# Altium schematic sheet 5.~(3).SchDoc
size 420 x 297 mm
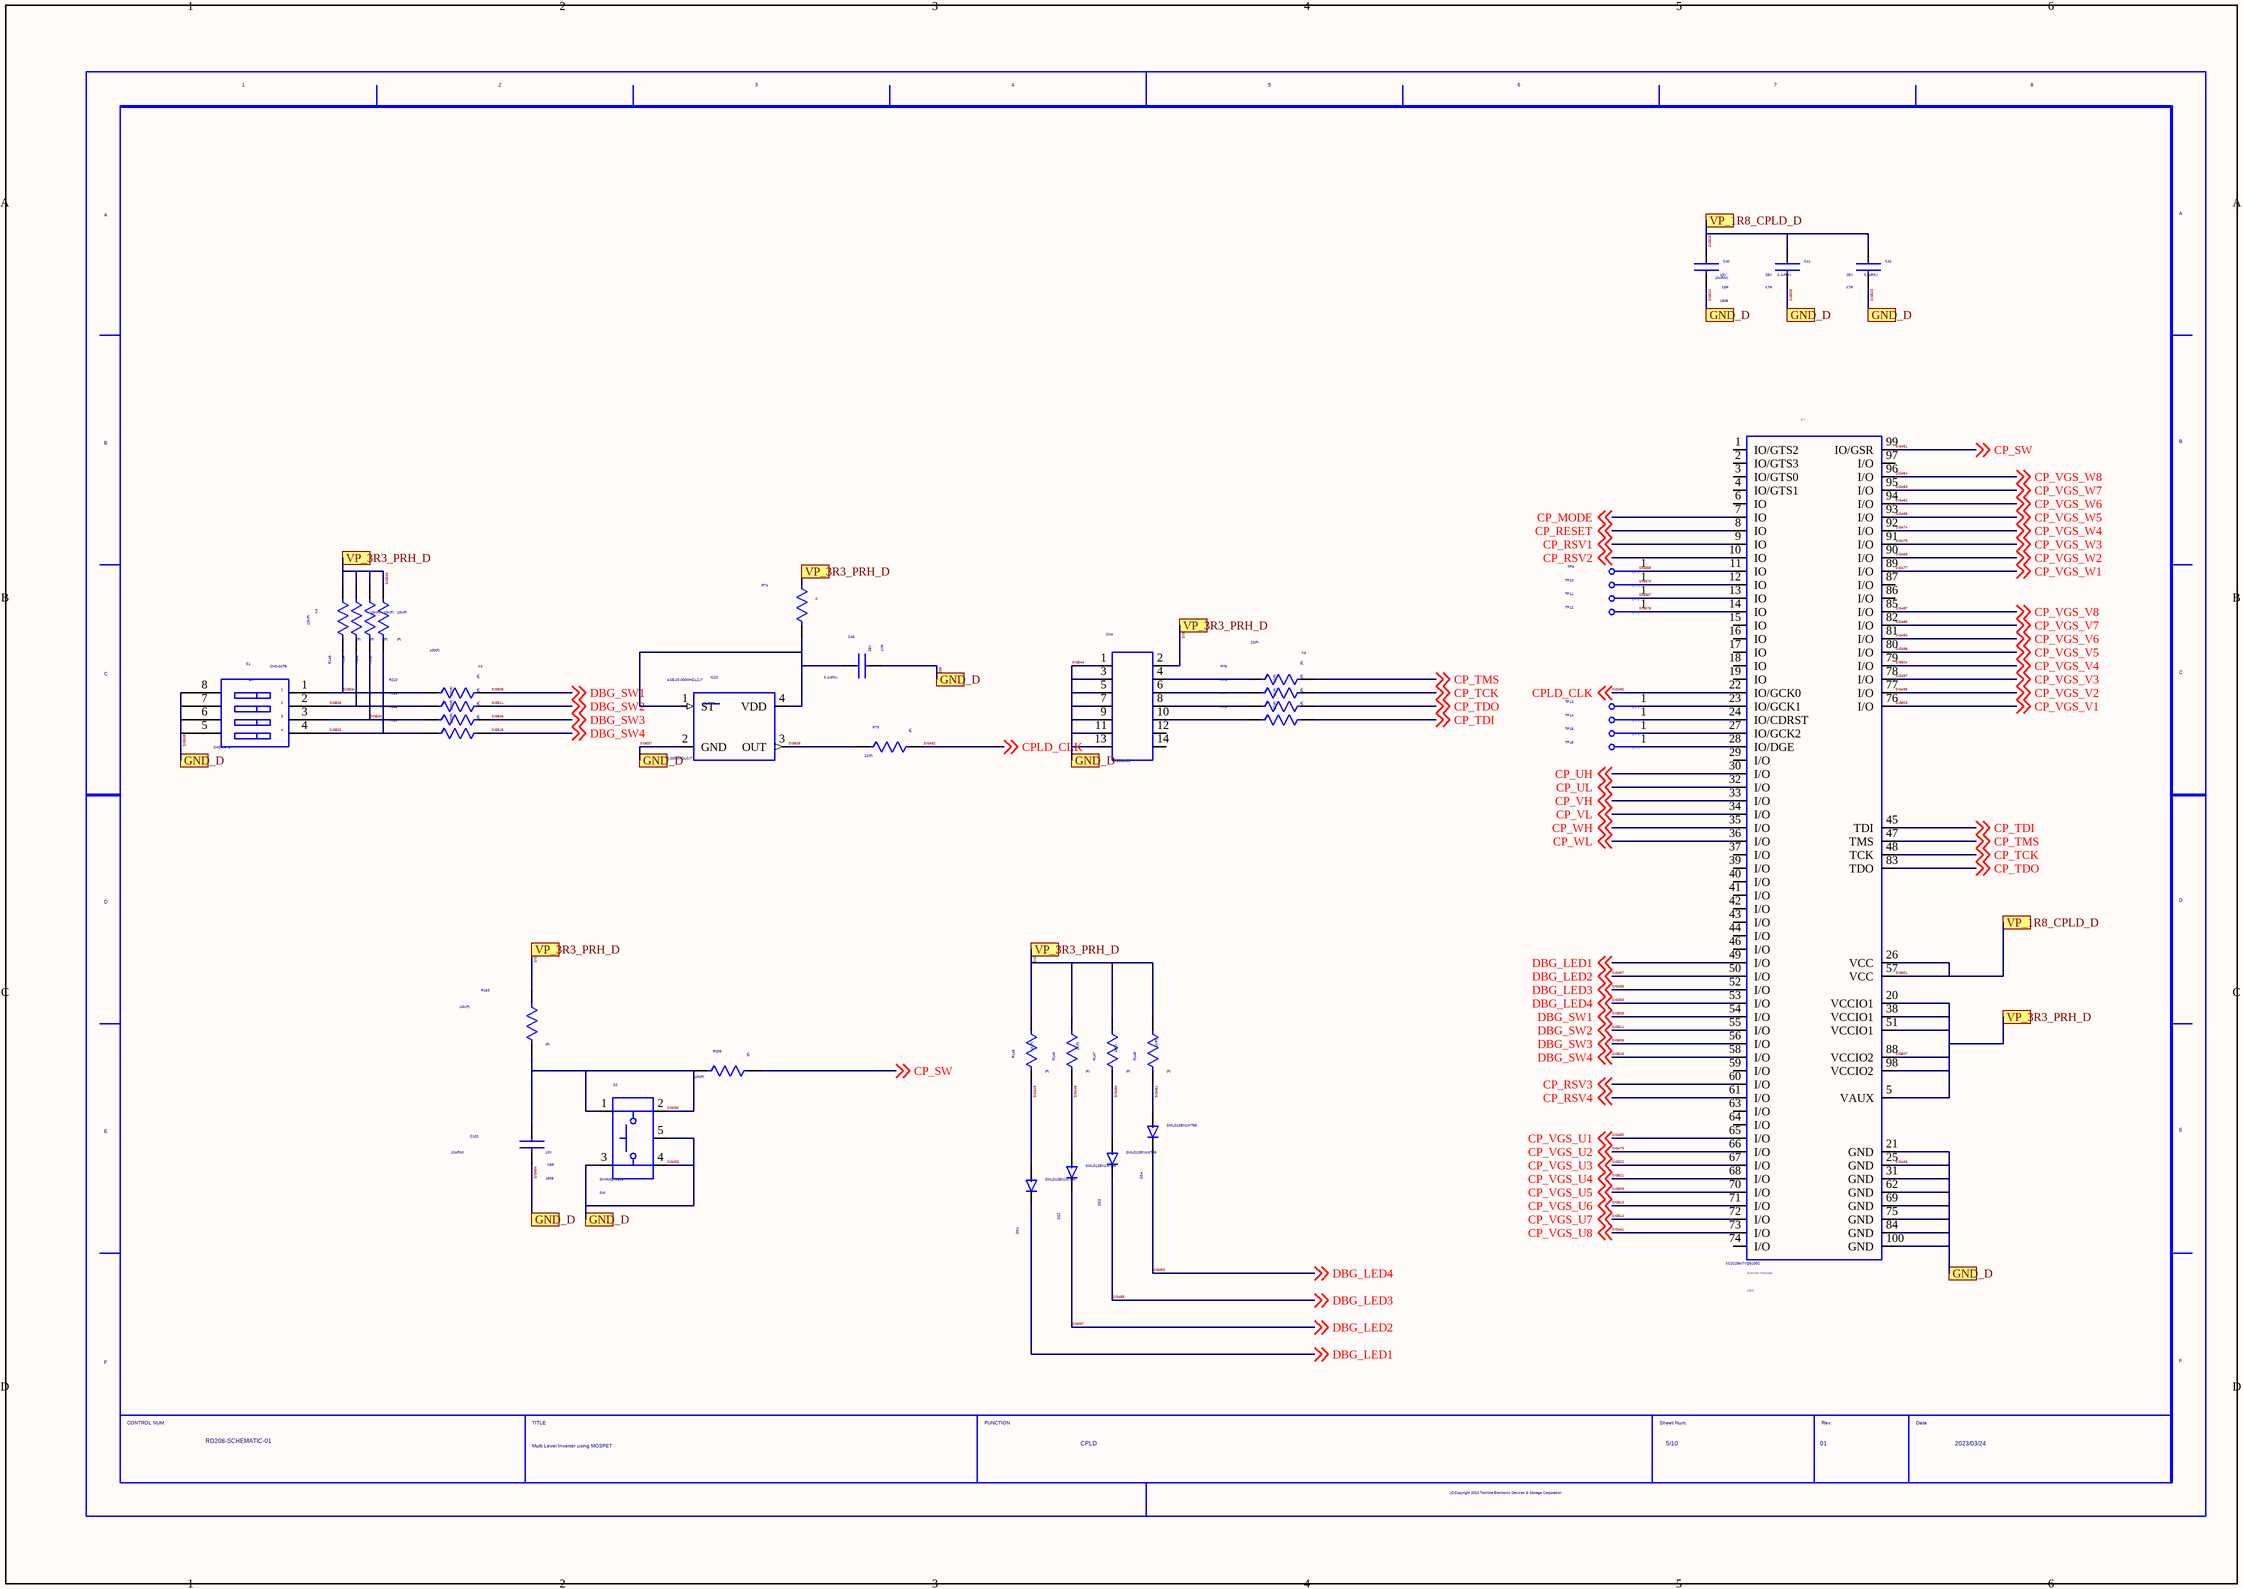
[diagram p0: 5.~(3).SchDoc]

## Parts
C40  VAL2: 10V  SIZECODESMD: 1608  VALUE4: X5R  VAL1: 10uF(M)  (hidden comment: GRM188R61A106ME69D)
C41  VAL2: 25V  VALUE4: X7R  VAL1: 0.1uF(K)  (hidden comment: GRM155R71E104KE14D)
C42  VAL2: 25V  VALUE4: X7R  VAL1: 0.1uF(K)  (hidden comment: GRM155R71E104KE14D)
C46  VAL2: 25V  VALUE4: X7R  VAL1: 0.1uF(K)  (hidden comment: GRM155R71E104KE14D)
C102  VAL2: 10V  SIZECODESMD: 1608  VALUE4: X5R  VAL1: 10uF(M)  (hidden comment: GRM188R61A106ME69D)
CN4  VAL1: 878311420  (hidden comment: 0878311420)
DS1  SMLD12EN1WT86
DS2  SMLD12EN1WT86
DS3  SMLD12EN1WT86
DS4  SMLD12EN1WT86
IC7  VAL2: CPLD  VAL1: XC2C256-7VQG100C  (hidden comment: XC2C256_7VQG100C)
IC22  VAL1: ASE-20.000MHZ-LC-T  (hidden comment: ASE_20_000MHZ_LC_T)
R74  VAL1: 0  (hidden comment: ERJ2GE0R00X)
R75  VALUE4: (F)  VAL1: 22(F)  (hidden comment: ERJ2RKF22R0X)
R76  VALUE4: (F)  VAL1: 22(F)  (hidden comment: ERJ2RKF22R0X)
R77  VALUE4: (F)  VAL1: 22(F)  (hidden comment: ERJ2RKF22R0X)
R78  VALUE4: (F)  VAL1: 22(F)  (hidden comment: ERJ2RKF22R0X)
R79  VALUE4: (F)  VAL1: 22(F)  (hidden comment: ERJ2RKF22R0X)
R145  VALUE4: (F)  VAL1: 1k(F)  (hidden comment: ERJ2RKF1001X)
R146  VALUE4: (F)  VAL1: 1k(F)  (hidden comment: ERJ2RKF1001X)
R147  VALUE4: (F)  VAL1: 1k(F)  (hidden comment: ERJ2RKF1001X)
R148  VALUE4: (F)  VAL1: 1k(F)  (hidden comment: ERJ2RKF1001X)
R149  VALUE4: (F)  VAL1: 10k(F)  (hidden comment: ERJ2RKF1002X)
R150  VALUE4: (F)  VAL1: 10k(F)  (hidden comment: ERJ2RKF1002X)
R151  VALUE4: (F)  VAL1: 10k(F)  (hidden comment: ERJ2RKF1002X)
R152  VALUE4: (F)  VAL1: 10k(F)  (hidden comment: ERJ2RKF1002X)
R153  VALUE4: (F)  VAL1: 10k(F)  (hidden comment: ERJ2RKF1002X)
R209  VALUE4: (F)  VAL1: 100(F)  (hidden comment: ERJ2RKF1000X)
R210  VALUE4: (F)  VAL1: 100(F)  (hidden comment: ERJ2RKF1000X)
R211  VALUE4: (F)  VAL1: 100(F)  (hidden comment: ERJ2RKF1000X)
R212  VALUE4: (F)  VAL1: 100(F)  (hidden comment: ERJ2RKF1000X)
R213  VALUE4: (F)  VAL1: 100(F)  (hidden comment: ERJ2RKF1000X)
S1  SCH_NAME: CHS-04TB  (hidden comment: CHS_04TB)
S2  VAL2: SW  (hidden comment: SKHMQKE010)
TP9  TP  (value not drawn)
TP10  TP  (value not drawn)
TP11  TP  (value not drawn)
TP12  TP  (value not drawn)
TP13  TP  (value not drawn)
TP14  TP  (value not drawn)
TP15  TP  (value not drawn)
TP16  TP  (value not drawn)
U?  DATE: 2023/03/24  REVISION: 01  SHEETNUMBER: 5/10  FUNCTION: CPLD  TITLE: Multi Level Inverter using MOSFET  DRAWINGNUMBER: RD208-SCHEMATIC-01  (hidden comment: WAKU_DEF100)

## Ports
GND_D, VP_1R8_CPLD_D, VP_3R3_PRH_D

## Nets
CP_MODE: IC7.7(IO) ; off-sheet CP_MODE
CP_RESET: IC7.8(IO) ; off-sheet CP_RESET
CP_RSV1: IC7.9(IO) ; off-sheet CP_RSV1
CP_RSV2: IC7.10(IO) ; off-sheet CP_RSV2
CP_RSV3: IC7.60(I/O) ; off-sheet CP_RSV3
CP_RSV4: IC7.61(I/O) ; off-sheet CP_RSV4
CP_TCK: IC7.48(TCK) R75.2 ; off-sheet CP_TCK
CP_TDI: IC7.45(TDI) R78.2 ; off-sheet CP_TDI
CP_TDO: IC7.83(TDO) R77.2 ; off-sheet CP_TDO
CP_TMS: IC7.47(TMS) R76.2 ; off-sheet CP_TMS
CP_UH: IC7.30(I/O) ; off-sheet CP_UH
CP_UL: IC7.32(I/O) ; off-sheet CP_UL
CP_VH: IC7.33(I/O) ; off-sheet CP_VH
CP_VL: IC7.34(I/O) ; off-sheet CP_VL
CP_WH: IC7.35(I/O) ; off-sheet CP_WH
CP_WL: IC7.36(I/O) ; off-sheet CP_WL
DBG_LED1: DS1.K(C) IC7.49(I/O) ; off-sheet DBG_LED1
SIG448: DS2.A R146.2
SIG449: DS1.A R145.2
SIG450: DS3.A R147.2
SIG451: DS4.A R148.2
SIG453: DS4.K(C) IC7.53(I/O) ; off-sheet DBG_LED4  [also labelled DBG_LED4]
SIG454: C40.2 C41.2 C42.2 C46.2 C102.2 CN4.1 CN4.3 CN4.5 CN4.7 CN4.9 CN4.11 CN4.13 IC7.21(GND) IC7.25(GND) IC7.31(GND) IC7.62(GND) IC7.69(GND) IC7.75(GND) IC7.84(GND) IC7.100(GND) IC22.2(GND) S1.5 S1.6 S1.7 S1.8 S2.3 S2.4 S2.5 ; port GND_D  [also labelled SIG459, SIG466, SIG523, SIG524, SIG525, SIG537, SIG538, SIG539, SIG544]
SIG455: DS3.K(C) IC7.52(I/O) ; off-sheet DBG_LED3  [also labelled DBG_LED3]
SIG456: C102.1 R153.2 R209.1 S2.1 S2.2
SIG457: DS2.K(C) IC7.50(I/O) ; off-sheet DBG_LED2  [also labelled DBG_LED2]
SIG458: CN4.2 IC7.5(VAUX) IC7.20(VCCIO1) IC7.38(VCCIO1) IC7.51(VCCIO1) IC7.88(VCCIO2) IC7.98(VCCIO2) R74.1 R145.1 R146.1 R147.1 R148.1 R149.1 R150.1 R151.1 R152.1 R153.1 ; port VP_3R3_PRH_D  [also labelled SIG460, SIG507, SIG531, SIG549]
SIG461: IC7.99(IO/GSR) R209.2 ; off-sheet CP_SW  [also labelled CP_SW]
SIG462: IC7.94(I/O) ; off-sheet CP_VGS_W6  [also labelled CP_VGS_W6]
SIG463: IC7.95(I/O) ; off-sheet CP_VGS_W7  [also labelled CP_VGS_W7]
SIG464: IC7.96(I/O) ; off-sheet CP_VGS_W8  [also labelled CP_VGS_W8]
SIG465: IC7.93(I/O) ; off-sheet CP_VGS_W5  [also labelled CP_VGS_W5]
SIG467: IC7.13(IO) TP11.1
SIG468: IC7.11(IO) TP9.1
SIG469: IC7.90(I/O) ; off-sheet CP_VGS_W2  [also labelled CP_VGS_W2]
SIG470: IC7.24(IO/CDRST) TP14.1
SIG471: IC7.23(IO/GCK1) TP13.1
SIG472: IC7.28(IO/DGE) TP16.1
SIG473: IC7.12(IO) TP10.1
SIG474: IC7.92(I/O) ; off-sheet CP_VGS_W4  [also labelled CP_VGS_W4]
SIG475: IC7.91(I/O) ; off-sheet CP_VGS_W3  [also labelled CP_VGS_W3]
SIG476: IC7.27(IO/GCK2) TP15.1
SIG477: IC7.89(I/O) ; off-sheet CP_VGS_W1  [also labelled CP_VGS_W1]
SIG478: IC7.14(IO) TP12.1
SIG479: IC7.66(I/O) ; off-sheet CP_VGS_U2  [also labelled CP_VGS_U2]
SIG480: IC7.65(I/O) ; off-sheet CP_VGS_U1  [also labelled CP_VGS_U1]
SIG481: IC7.73(I/O) ; off-sheet CP_VGS_U8  [also labelled CP_VGS_U8]
SIG485: IC7.82(I/O) ; off-sheet CP_VGS_V7  [also labelled CP_VGS_V7]
SIG487: IC7.85(I/O) ; off-sheet CP_VGS_V8  [also labelled CP_VGS_V8]
SIG492: IC7.22(IO/GCK0) R79.2 ; off-sheet CPLD_CLK  [also labelled CPLD_CLK]
SIG493: IC7.81(I/O) ; off-sheet CP_VGS_V6  [also labelled CP_VGS_V6]
SIG495: IC7.77(I/O) ; off-sheet CP_VGS_V2  [also labelled CP_VGS_V2]
SIG497: IC7.78(I/O) ; off-sheet CP_VGS_V3  [also labelled CP_VGS_V3]
SIG498: IC7.80(I/O) ; off-sheet CP_VGS_V5  [also labelled CP_VGS_V5]
SIG501: C40.1 C41.1 C42.1 IC7.26(VCC) IC7.57(VCC) ; port VP_1R8_CPLD_D  [also labelled SIG526]
SIG503: IC7.76(I/O) ; off-sheet CP_VGS_V1  [also labelled CP_VGS_V1]
SIG504: IC7.79(I/O) ; off-sheet CP_VGS_V4  [also labelled CP_VGS_V4]
SIG506: IC7.56(I/O) R212.2 ; off-sheet DBG_SW3  [also labelled DBG_SW3]
SIG508: IC7.54(I/O) R210.2 ; off-sheet DBG_SW1  [also labelled DBG_SW1]
SIG509: IC7.70(I/O) ; off-sheet CP_VGS_U5  [also labelled CP_VGS_U5]
SIG511: IC7.55(I/O) R211.2 ; off-sheet DBG_SW2  [also labelled DBG_SW2]
SIG513: IC7.71(I/O) ; off-sheet CP_VGS_U6  [also labelled CP_VGS_U6]
SIG514: IC7.72(I/O) ; off-sheet CP_VGS_U7  [also labelled CP_VGS_U7]
SIG515: IC7.58(I/O) R213.2 ; off-sheet DBG_SW4  [also labelled DBG_SW4]
SIG521: IC7.68(I/O) ; off-sheet CP_VGS_U4  [also labelled CP_VGS_U4]
SIG522: IC7.67(I/O) ; off-sheet CP_VGS_U3  [also labelled CP_VGS_U3]
SIG530: C46.1 IC22.1(ST) IC22.4(VDD) R74.2
SIG532: R152.2 R213.1 S1.4
SIG533: R151.2 R212.1 S1.3
SIG534: R149.2 R210.1 S1.1
SIG535: IC22.3(OUT) R79.1
SIG536: R150.2 R211.1 S1.2
SIG540: CN4.10 R78.1
SIG541: CN4.6 R75.1
SIG542: CN4.4 R76.1
SIG543: CN4.8 R77.1

Not connected (* = marked no-connect by the designer): CN4 12 14; IC7 1(IO/GTS2) 2(IO/GTS3) 3(IO/GTS0) 4(IO/GTS1) 6(IO) 15(IO) 16(IO) 17(IO) 18(IO) 19(IO) 29(I/O) 37(I/O) 39(I/O) 40(I/O) 41(I/O) 42(I/O) 43(I/O) 44(I/O) 46(I/O) 59(I/O) 63(I/O) 64(I/O) 74(I/O) 86(I/O) 87(I/O) 97(I/O)

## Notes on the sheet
- X4

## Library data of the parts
C40 = GRM188R61A106ME69D: MANUFACTURER: MURATA; ITEM: CAP Ceramic; TIME: 08:44:46; UPDATEUSER: t5459927; SAVECOUNT: 1; OriginalSymbolOrigin: (0,0); INSTANCENAME: INS15854292
C41 = GRM155R71E104KE14D: MANUFACTURER: MURATA; ITEM: CAP Ceramic; SIZECODESMD: 1005; TIME: 08:44:45; UPDATEUSER: t5459927; SAVECOUNT: 1; OriginalSymbolOrigin: (0,0); INSTANCENAME: INS15854312
C42 = GRM155R71E104KE14D: MANUFACTURER: MURATA; ITEM: CAP Ceramic; SIZECODESMD: 1005; TIME: 08:44:45; UPDATEUSER: t5459927; SAVECOUNT: 1; OriginalSymbolOrigin: (0,0); INSTANCENAME: INS15854332
C46 = GRM155R71E104KE14D: MANUFACTURER: MURATA; ITEM: CAP Ceramic; SIZECODESMD: 1005; TIME: 08:44:45; UPDATEUSER: t5459927; SAVECOUNT: 1; OriginalSymbolOrigin: (0,0); INSTANCENAME: INS15966208
C102 = GRM188R61A106ME69D: MANUFACTURER: MURATA; ITEM: CAP Ceramic; TIME: 08:44:46; UPDATEUSER: t5459927; SAVECOUNT: 1; OriginalSymbolOrigin: (0,0); INSTANCENAME: INS15982721
CN4 = 0878311420: MANUFACTURER: Molex; ITEM: Connector; TIME: 08:44:46; UPDATEUSER: t5459927; SAVECOUNT: 1; SAVEAREA0: -11456,-20726,18408,1136; OriginalSymbolOrigin: (0,0); INSTANCENAME: INS15810166
DS1 = SMLD12EN1WT86: MANUFACTURER: ROHM; ITEM: LED; VAL2: GREEN; SIZECODESMD: 1608; TIME: 08:44:46; UPDATEUSER: t5459927; SAVECOUNT: 1; OriginalSymbolOrigin: (0,0); INSTANCENAME: INS16374367
DS2 = SMLD12EN1WT86: MANUFACTURER: ROHM; ITEM: LED; VAL2: GREEN; SIZECODESMD: 1608; TIME: 08:44:46; UPDATEUSER: t5459927; SAVECOUNT: 1; OriginalSymbolOrigin: (0,0); INSTANCENAME: INS16374465
DS3 = SMLD12EN1WT86: MANUFACTURER: ROHM; ITEM: LED; VAL2: GREEN; SIZECODESMD: 1608; TIME: 08:44:46; UPDATEUSER: t5459927; SAVECOUNT: 1; OriginalSymbolOrigin: (0,0); INSTANCENAME: INS16374497
DS4 = SMLD12EN1WT86: MANUFACTURER: ROHM; ITEM: LED; VAL2: GREEN; SIZECODESMD: 1608; TIME: 08:44:46; UPDATEUSER: t5459927; SAVECOUNT: 1; OriginalSymbolOrigin: (0,0); INSTANCENAME: INS16374529
IC7 = XC2C256_7VQG100C: MANUFACTURER: Xilinx; ITEM: IC CPLD; TIME: 08:44:46; UPDATEUSER: PS4_common_PC; UPDATETIME: 16:00:18; SAVECOUNT: 3; SAVEAREA0: -110321,-158692,133213,-47724; OriginalSymbolOrigin: (0,0)
IC22 = ASE_20_000MHZ_LC_T: MANUFACTURER: Abracon; ITEM: Crystal  Oscillator; VAL2: 20.0MHz; SIZECODESMD: 3225; VALUE4: 50ppm; TIME: 08:44:46; UPDATEUSER: PS4_common_PC; UPDATETIME: 16:08:33; SAVECOUNT: 3; SAVEAREA0: -31083,-23837,46439,11486; OriginalSymbolOrigin: (0,0)
R74 = ERJ2GE0R00X: MANUFACTURER: Panasonic; ITEM: Register; VAL2: 1/10W; SIZECODESMD: 1005; TIME: 08:44:45; UPDATEUSER: t5459927; SAVECOUNT: 1; OriginalSymbolOrigin: (0,0); INSTANCENAME: INS15966188
R75 = ERJ2RKF22R0X: MANUFACTURER: Panasonic; ITEM: Register; VAL2: 100mW; SIZECODESMD: 1005; TIME: 08:44:46; UPDATEUSER: t5459927; SAVECOUNT: 1; OriginalSymbolOrigin: (0,0); INSTANCENAME: INS15815381
R76 = ERJ2RKF22R0X: MANUFACTURER: Panasonic; ITEM: Register; VAL2: 100mW; SIZECODESMD: 1005; TIME: 08:44:46; UPDATEUSER: t5459927; SAVECOUNT: 1; OriginalSymbolOrigin: (0,0); INSTANCENAME: INS15815301
R77 = ERJ2RKF22R0X: MANUFACTURER: Panasonic; ITEM: Register; VAL2: 100mW; SIZECODESMD: 1005; TIME: 08:44:46; UPDATEUSER: t5459927; SAVECOUNT: 1; OriginalSymbolOrigin: (0,0); INSTANCENAME: INS15815427
R78 = ERJ2RKF22R0X: MANUFACTURER: Panasonic; ITEM: Register; VAL2: 100mW; SIZECODESMD: 1005; TIME: 08:44:46; UPDATEUSER: t5459927; SAVECOUNT: 1; OriginalSymbolOrigin: (0,0); INSTANCENAME: INS15815473
R79 = ERJ2RKF22R0X: MANUFACTURER: Panasonic; ITEM: Register; VAL2: 100mW; SIZECODESMD: 1005; TIME: 08:44:46; UPDATEUSER: t5459927; SAVECOUNT: 1; OriginalSymbolOrigin: (0,0); INSTANCENAME: INS15966292
R145-R148 = ERJ2RKF1001X: MANUFACTURER: Panasonic; ITEM: Register; VAL2: 100mW; SIZECODESMD: 1005; TIME: 08:44:45; UPDATEUSER: t5459927; SAVECOUNT: 1; OriginalSymbolOrigin: (0,0); INSTANCENAME: INS17200488
R149 = ERJ2RKF1002X: MANUFACTURER: Panasonic; ITEM: Register; VAL2: 100mW; SIZECODESMD: 1005; TIME: 08:44:45; UPDATEUSER: t5459927; SAVECOUNT: 1; OriginalSymbolOrigin: (0,0); INSTANCENAME: INS17131726
R150 = ERJ2RKF1002X: MANUFACTURER: Panasonic; ITEM: Register; VAL2: 100mW; SIZECODESMD: 1005; TIME: 08:44:45; UPDATEUSER: t5459927; SAVECOUNT: 1; OriginalSymbolOrigin: (0,0); INSTANCENAME: INS17131576
R151 = ERJ2RKF1002X: MANUFACTURER: Panasonic; ITEM: Register; VAL2: 100mW; SIZECODESMD: 1005; TIME: 08:44:45; UPDATEUSER: t5459927; SAVECOUNT: 1; OriginalSymbolOrigin: (0,0); INSTANCENAME: INS17131426
R152 = ERJ2RKF1002X: MANUFACTURER: Panasonic; ITEM: Register; VAL2: 100mW; SIZECODESMD: 1005; TIME: 08:44:45; UPDATEUSER: t5459927; SAVECOUNT: 1; OriginalSymbolOrigin: (0,0); INSTANCENAME: INS17130644
R153 = ERJ2RKF1002X: MANUFACTURER: Panasonic; ITEM: Register; VAL2: 100mW; SIZECODESMD: 1005; TIME: 08:44:45; UPDATEUSER: t5459927; SAVECOUNT: 1; OriginalSymbolOrigin: (0,0); INSTANCENAME: INS15982142
R209 = ERJ2RKF1000X: MANUFACTURER: Panasonic; ITEM: Register; VAL2: 100mW; SIZECODESMD: 1005; TIME: 08:44:46; UPDATEUSER: t5459927; SAVECOUNT: 1; OriginalSymbolOrigin: (0,0); INSTANCENAME: INS16644148
R210 = ERJ2RKF1000X: MANUFACTURER: Panasonic; ITEM: Register; VAL2: 100mW; SIZECODESMD: 1005; TIME: 08:44:46; UPDATEUSER: t5459927; SAVECOUNT: 1; OriginalSymbolOrigin: (0,0); INSTANCENAME: INS16645400
R211 = ERJ2RKF1000X: MANUFACTURER: Panasonic; ITEM: Register; VAL2: 100mW; SIZECODESMD: 1005; TIME: 08:44:46; UPDATEUSER: t5459927; SAVECOUNT: 1; OriginalSymbolOrigin: (0,0); INSTANCENAME: INS16645432
R212 = ERJ2RKF1000X: MANUFACTURER: Panasonic; ITEM: Register; VAL2: 100mW; SIZECODESMD: 1005; TIME: 08:44:46; UPDATEUSER: t5459927; SAVECOUNT: 1; OriginalSymbolOrigin: (0,0); INSTANCENAME: INS16645464
R213 = ERJ2RKF1000X: MANUFACTURER: Panasonic; ITEM: Register; VAL2: 100mW; SIZECODESMD: 1005; TIME: 08:44:46; UPDATEUSER: t5459927; SAVECOUNT: 1; OriginalSymbolOrigin: (0,0); INSTANCENAME: INS16645496
S1 = CHS_04TB: MANUFACTURER: COPAL; ITEM: DIP Switch 4P; VAL2: 50V 100mA; TIME: 08:44:46; UPDATEUSER: t5459927; SAVECOUNT: 1; SAVEAREA0: -8722,-16798,20771,4793; OriginalSymbolOrigin: (0,0); INSTANCENAME: INS16410549
S2 = SKHMQKE010: MANUFACTURER: ALPS; ITEM: Tactile Switch SMD; TIME: 08:44:46; UPDATEUSER: t5459927; SAVECOUNT: 1; OriginalSymbolOrigin: (0,0); INSTANCENAME: INS16410953
TP9-TP16 = TP: TIME: 16:12:21; UPDATEUSER: fukuda-y; UPDATETIME: 16:18:11; SAVECOUNT: 2; SAVEAREA0: -242,-92,12810,7836; OriginalSymbolOrigin: (0,7620); VAL3: TH Hole dia. 1.0; COMP: TP-TH1.0-L1.6
U? = WAKU_DEF100: PLOTTIME: HH:MM; SAVEAREA0: 185750,-43960,448537,75779; TIME: 14:30:25; UPDATEUSER: PS4_common_PC; UPDATETIME: 08:24:48; SAVECOUNT: 8; OriginalSymbolOrigin: (10160,284480)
